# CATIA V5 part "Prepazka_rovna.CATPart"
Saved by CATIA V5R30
Part number: Prepazka_rovna
Definition: E 21000_12_125__l_cut_to_length_80_1
Nomenclature: E 21000_12_125__l_cut_to_length_80_1
Source: Unknown
Description: PART-E 21000_12_125__l_cut_to_length_80_1-DESC
Bounding box of the stored display mesh (mm): x -6 to 6, y -6 to 6, z 0 to 88
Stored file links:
  E:\Bakalarka\Model\Forma_v7\Prepazka_rovna.CATPart
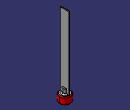
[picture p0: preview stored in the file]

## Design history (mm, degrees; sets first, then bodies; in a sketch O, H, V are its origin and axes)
Body1 "E 21000_12_125__l_cut_to_length_80" (main body)
  Solid1: solid without history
